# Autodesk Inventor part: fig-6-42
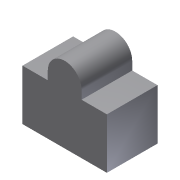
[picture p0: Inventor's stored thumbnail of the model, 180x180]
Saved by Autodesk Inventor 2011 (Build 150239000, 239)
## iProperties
Created: 2005-12
Part Number: fig-6-42
Document SubType Name: Modeling
Designer: CADCIM
Density: 1 g/cm^3
Author: CADCIM
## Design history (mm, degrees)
sketch "Sketch1"
  geometry: L1 (10, 15)-(25, 15); L2 (25, 15)-(25, -15); L3 (25, -15)-(-25, -15); L4 (-25, -15)-(-25, 15); L5 (-25, 15)-(-10, 15); L6 (10, 15)-(10, 30); L7 (10, 30)-(-10, 30); L8 (-10, 30)-(-10, 15)
  constraints: 16 end point, 3 parallel, 3 perpendicular, 2 equal length, 1 collinear, 1 horizontal
  dimensions: "d0" = 50 distance of L2.end L3.end; "d2" = 30 distance of L1.end L2.end; "d3" = 15 distance of L1.start L1.end; "d11" = 15 distance of L7.end L5.end
extrude "Extrusion1" new body sketch "Sketch1" stored distance "d7" = 30; taper "d8" = 0 deg
fillet "Fillet5"
body "Solid1"
